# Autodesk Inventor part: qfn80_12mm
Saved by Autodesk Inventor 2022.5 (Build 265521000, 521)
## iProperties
Created: 2024-12
Part Number: qfn80_12mm
Material: Generic
Document SubType Name: Modeling
Designer: AdminForWorker
Density: 1 g/cm^3
Appearance: Default
Title: qfn80_12mm v1
Author: AdminForWorker
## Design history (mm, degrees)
feature "Body1"
feature "Body64"
feature "Body112"
feature "Body113"
feature "Body114"
feature "Body115"
feature "Body65"
feature "Body66"
feature "Body67"
feature "Body68"
feature "Body69"
feature "Body70"
feature "Body71"
feature "Body72"
feature "Body73"
feature "Body74"
feature "Body75"
feature "Body116"
feature "Body117"
feature "Body118"
feature "Body119"
feature "Body106"
feature "Body120"
feature "Body121"
feature "Body122"
feature "Body123"
feature "Body109"
feature "Body103"
feature "Body100"
feature "Body97"
feature "Body94"
feature "Body91"
feature "Body88"
feature "Body85"
feature "Body82"
feature "Body79"
feature "Body76"
feature "Body124"
feature "Body125"
feature "Body126"
feature "Body127"
feature "Body107"
feature "Body128"
feature "Body129"
feature "Body130"
feature "Body131"
feature "Body110"
feature "Body104"
feature "Body101"
feature "Body98"
feature "Body95"
feature "Body92"
feature "Body89"
feature "Body86"
feature "Body83"
feature "Body80"
feature "Body77"
feature "Body132"
feature "Body133"
feature "Body134"
feature "Body135"
feature "Body108"
feature "Body136"
feature "Body137"
feature "Body138"
feature "Body139"
feature "Body111"
feature "Body105"
feature "Body102"
feature "Body99"
feature "Body96"
feature "Body93"
feature "Body90"
feature "Body87"
feature "Body84"
feature "Body81"
feature "Body78"
feature "Body140"
feature "Body141"
feature "Body142"
feature "Body143"
body "Solid1"
body "Solid2"
body "Solid3"
body "Solid4"
body "Solid5"
body "Solid6"
body "Solid7"
body "Solid8"
body "Solid9"
body "Solid10"
body "Solid11"
body "Solid12"
body "Solid13"
body "Solid14"
body "Solid15"
body "Solid16"
body "Solid17"
body "Solid18"
body "Solid19"
body "Solid20"
body "Solid21"
body "Solid22"
body "Solid23"
body "Solid24"
body "Solid25"
body "Solid26"
body "Solid27"
body "Solid28"
body "Solid29"
body "Solid30"
body "Solid31"
body "Solid32"
body "Solid33"
body "Solid34"
body "Solid35"
body "Solid36"
body "Solid37"
body "Solid38"
body "Solid39"
body "Solid40"
body "Solid41"
body "Solid42"
body "Solid43"
body "Solid44"
body "Solid45"
body "Solid46"
body "Solid47"
body "Solid48"
body "Solid49"
body "Solid50"
body "Solid51"
body "Solid52"
body "Solid53"
body "Solid54"
body "Solid55"
body "Solid56"
body "Solid57"
body "Solid58"
body "Solid59"
body "Solid60"
body "Solid61"
body "Solid62"
body "Solid63"
body "Solid64"
body "Solid65"
body "Solid66"
body "Solid67"
body "Solid68"
body "Solid69"
body "Solid70"
body "Solid71"
body "Solid72"
body "Solid73"
body "Solid74"
body "Solid75"
body "Solid76"
body "Solid77"
body "Solid78"
body "Solid79"
body "Solid80"
body "Solid81"
